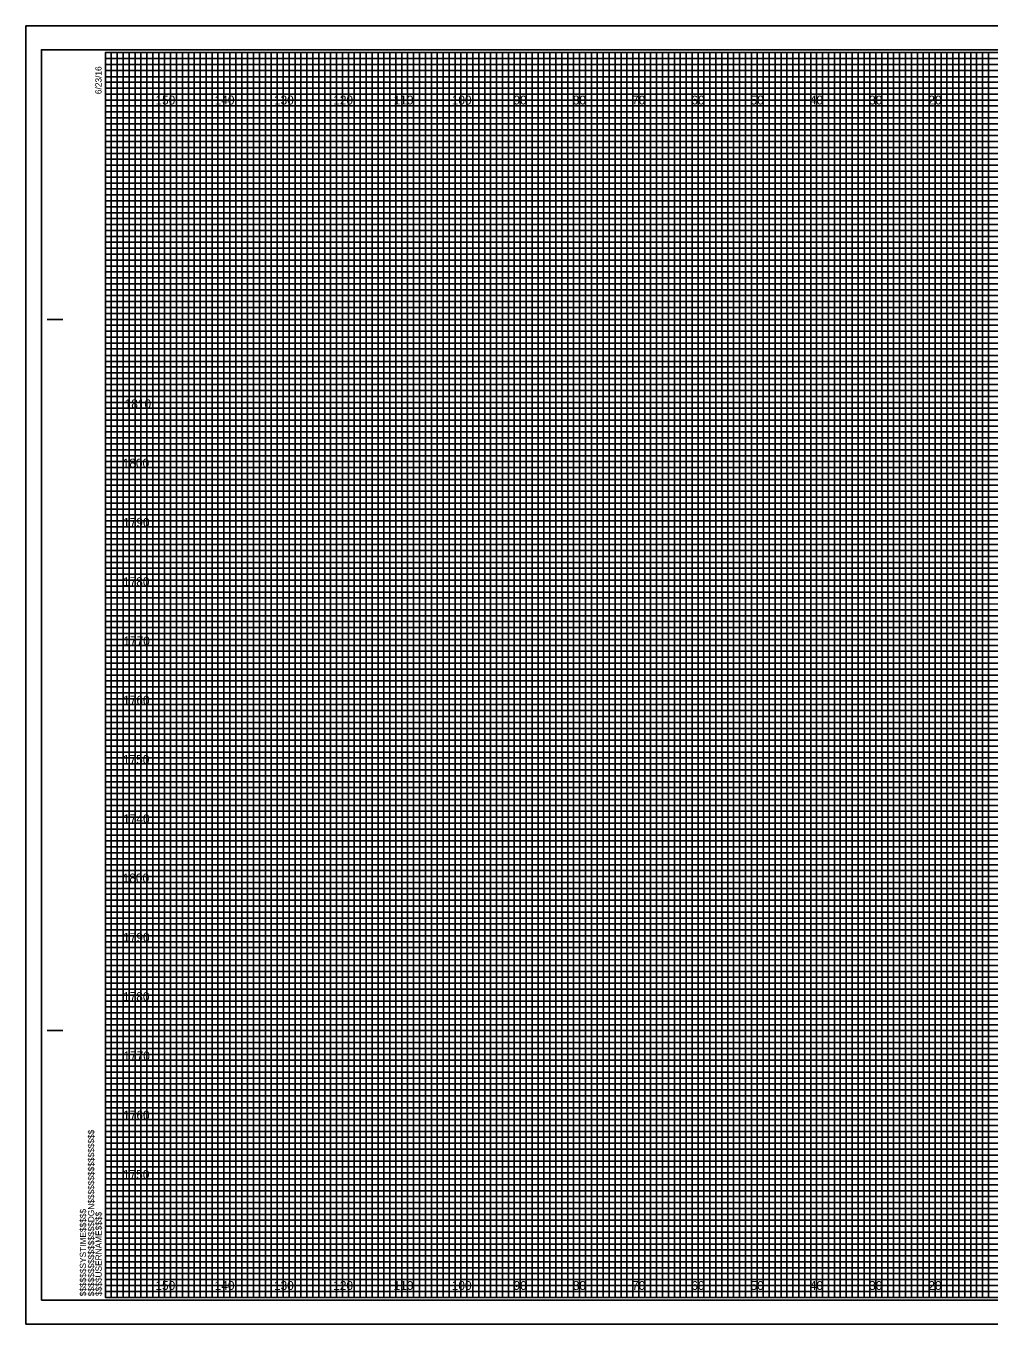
# Model space of a CAD drawing. Extents: x -13 to 323, y -5 to 874.
# Drawn here: x -13.4 to 149.1, y 435.5 to 654.5 of the extents above; entities that cross this region are included whole.
import ezdxf

# ---------------------------------------------------------------- set-up
doc = ezdxf.new("R2010")
doc.units = 0
for name, color, linetype in [('Prop XS DDE', 7, 'Continuous'), ('Prop XS DDE Elevations', 7, 'Continuous'), ('Prop XS DDE Slope Text', 7, 'Continuous'), ('Prop XS Gore Control Minimum', 7, 'Continuous'), ('Prop XS Shoulder Borrow Shape', 7, 'Continuous'), ('Raster_Level_0', 7, 'Continuous'), ('Scratch_Level_3', 7, 'Continuous'), ('Sheet Cutting Line CELL', 7, 'Continuous'), ('Sheet DOT Grid CELL', 7, 'Continuous'), ('Sheet Plot Border Inside CELL', 7, 'Continuous'), ('Sheet Plot Border Outside CELL', 7, 'Continuous')]:
    doc.layers.add(name, color=color, linetype=linetype)

msp = doc.modelspace()

# ---------------------------------------------------------------- linework, layer by layer
at = {"layer": 'Prop XS DDE'}
for p, q in [((0, 649), (260, 649)), ((260, 647.98), (0, 647.98)), ((0, 647.98), (0, 647)), ((0, 647), (260, 647)), ((260, 645.89), (0, 645.89)), ((0, 645.89), (0, 644)), ((0, 644), (320, 644))]:
    msp.add_line(p, q, dxfattribs=at)
for points in [[(0, 643), (270, 643), (320, 643), (320, 642), (0, 642)], [(0, 641), (320, 641), (320, 639), (0, 639)], [(0, 638), (320, 638), (320, 637), (0, 636.98)], [(0, 636), (320, 636), (320, 634), (0, 634)], [(0, 633), (320, 633), (320, 632), (0, 632)], [(0, 631), (320, 631), (320, 629), (0, 629)], [(0, 628), (320, 628), (320, 627), (0, 627)], [(0, 626), (320, 626), (320, 624), (0, 624)], [(0, 623), (320, 623), (320, 622), (0, 622)], [(0, 621), (320, 621), (320, 619), (0, 619)], [(0, 618), (320, 618), (320, 617), (0, 617)], [(0, 616), (320, 616), (320, 613.95), (320, 613), (320, 612), (0, 612)], [(0, 614), (320, 614), (320, 613), (0, 613)], [(0, 611), (320, 611), (320, 609), (0, 609.03)], [(0, 609.03), (320, 609), (320, 608), (0, 608)], [(0, 607), (320, 607), (320, 606), (0, 606)], [(0, 604), (320, 604), (320, 603), (0, 603)], [(0, 602), (320, 602), (320, 601), (0, 601)], [(-0.07, 598.89), (320, 598.89), (320, 597.88), (-0.07, 597.88)], [(0, 597), (320, 597), (320, 596), (0, 596)], [(0, 594), (320, 594), (320, 593), (0, 593)], [(0, 592), (320, 592), (320, 591), (0, 591)], [(0, 589), (320, 589), (320, 588), (0, 588)], [(0, 587), (320, 587), (320, 586), (0, 586)], [(0, 584), (320, 584), (320, 583), (0, 583)], [(0, 582), (320, 582), (320, 581), (0, 581)], [(0, 579), (320, 579), (319.99, 577.98), (0, 578)], [(0, 577), (320, 577), (320, 576), (0, 576)], [(0, 574), (320, 574), (320, 573), (0, 573)], [(0, 572), (320, 572), (320, 571), (0, 571)], [(0, 569), (320, 569), (320, 568), (0, 568)], [(0, 567), (320, 567), (320, 566), (0, 566)], [(0, 564), (320, 564), (320, 563), (0, 563)], [(0, 562), (320, 562), (320, 561), (0, 561)], [(0, 559), (320, 559), (320, 558), (0, 558)], [(0, 556.99), (320.07, 556.91), (320, 556), (0, 556)], [(0, 554), (320, 554), (320, 553), (0, 553)], [(0, 552), (320, 552), (320, 551), (0, 551)], [(0, 549), (320, 549), (320, 548), (0, 548)], [(0, 547), (320, 547), (320, 546), (0, 546)], [(0, 544), (320, 544), (320, 543), (0, 543)], [(0, 542), (320, 542), (320, 541), (0, 541)], [(0, 539), (320, 539), (320, 538), (0, 538)], [(0, 537), (320, 537), (320, 536), (0, 536)], [(0, 534), (320, 534), (320, 533), (0, 533)], [(0, 532), (320, 532), (320, 531), (0, 531)], [(0, 529), (320, 529), (320, 528), (0, 528)], [(0, 527), (320, 527), (320, 526), (0, 526)], [(0, 524), (320, 524), (320, 523), (0, 523)], [(0, 522), (320, 522), (320, 521), (0, 521)], [(0, 519), (320, 519), (319.99, 517.98), (0, 518)], [(0, 517), (320, 517), (320, 516), (0, 516)], [(0, 514), (320, 514), (320, 513), (0, 513)], [(0, 512), (320, 512), (320, 511), (0, 511)], [(0, 509), (320, 509), (320, 508), (0, 508)], [(0, 507), (320, 507), (320, 506), (0, 506)], [(0, 504), (320, 504), (320, 503), (0, 503)], [(0, 502), (320, 502), (320, 501), (0, 501)], [(0, 499), (320, 499), (320, 498), (0, 498)], [(0, 496.99), (320.07, 496.91), (320, 496), (0, 496)], [(0, 494), (320, 494), (320, 493), (0, 493)], [(0, 492), (320, 492), (320, 491), (0, 491)], [(0, 489), (320, 489), (320, 488), (0, 488)], [(0, 487), (320, 487), (320, 486), (0, 486)], [(0, 484), (320, 484), (320, 483), (0, 483)], [(0, 482), (320, 482), (320, 481), (0, 481)], [(0, 479), (320, 479), (320, 478), (0, 478)], [(0, 477), (320, 477), (320, 476), (0, 476)], [(0, 474), (320, 474), (320, 473), (0, 473)], [(0, 472), (320, 472), (320, 471), (0, 471)], [(0, 469), (320, 469), (320, 468), (0, 468)], [(0, 467), (320, 467), (320, 466), (0, 466)], [(0, 464), (320, 464), (320, 463), (0, 463)], [(0, 462), (320, 462), (320, 461), (0, 461)], [(0, 459), (320, 459), (320, 458), (0, 458)], [(0, 457), (320, 457), (320, 456), (0, 456)], [(0, 454), (320, 454), (320, 453), (0, 453)], [(0, 452), (320, 452), (320, 451), (0, 451)], [(0, 449), (320, 449), (320, 448), (0, 448)], [(0, 447), (320, 447), (320, 446), (0, 446)], [(0, 444), (320, 444), (320, 443), (0, 443)], [(0, 442), (320, 442), (320, 441), (0, 441)]]:
    msp.add_lwpolyline(points, dxfattribs=at)
at = {"layer": 'Prop XS DDE Elevations'}
for points in [[(0, 440), (1, 440), (1, 650), (2, 650), (2, 440)], [(2, 440), (3, 440), (3, 650), (4, 650), (4, 440)], [(5, 440), (6, 440), (6, 650), (7, 650), (7, 440)], [(7, 440), (8, 440), (8, 650), (9, 650), (9, 440)], [(10, 440), (11, 440), (11, 650), (12, 650), (12, 440)], [(12, 440), (13, 440), (13, 650), (14, 650), (14, 440)], [(15, 440), (16, 440), (16, 650), (17, 650), (17, 440)], [(17, 440), (18, 440), (18, 650), (19, 650), (19, 440)], [(20, 440), (21, 440), (21, 650), (22, 650), (22, 440)], [(22, 440), (23, 440), (23, 650), (24, 650), (24, 440)], [(25, 440), (26, 440), (26, 650), (27, 650), (27, 440)], [(27, 440), (28, 440), (28, 650), (29, 650), (29, 440)], [(30, 440), (31, 440), (31, 650), (32, 650), (32, 440)], [(32, 440), (33, 440), (33, 650), (34, 650), (34, 440)], [(35, 440), (36, 440), (36, 650), (37, 650), (37, 440)], [(37, 440), (38, 440), (38, 650), (39, 650), (39, 440)], [(40, 440), (41, 440), (41, 650), (42, 650), (42, 440)], [(42, 440), (43, 440), (43, 650), (44, 650), (44, 440)], [(45, 440), (46, 440), (46, 650), (47, 650), (47, 440)], [(47, 440), (48, 440), (48, 650), (49, 650), (49, 440)], [(50, 440), (51, 440), (51, 650), (52, 650), (52, 440)], [(52, 440), (53, 440), (53, 650), (54, 650), (54, 440)], [(55, 440), (56, 440), (56, 650), (57, 650), (57, 440)], [(57, 440), (58, 440), (58, 650), (59, 650), (59, 440)], [(60, 440), (61, 440), (61, 650), (62, 650), (62, 440)], [(62, 440), (63, 440), (63, 650), (64, 650), (64, 440)], [(65, 440), (66, 440), (66, 650), (67, 650), (67, 440)], [(67, 440), (68, 440), (68, 650), (69, 650), (69, 440)], [(70, 440), (71, 440), (71, 650), (72, 650), (72, 440)], [(72, 440), (73, 440), (73, 650), (74, 650), (74, 440)], [(75, 440), (76, 440), (76, 650), (77, 650), (77, 440)], [(77, 440), (78, 440), (78, 650), (79, 650), (79, 440)], [(80, 440), (81, 440), (81, 650), (82, 650), (82, 440)], [(82, 440), (83, 440), (83, 650), (84, 650), (84, 440)], [(85, 440), (86, 440), (86, 650), (87, 650), (87, 440)], [(87, 440), (88, 440), (88, 650), (89, 650), (89, 440)], [(90, 440), (91, 440), (91, 650), (92, 650), (92, 440)], [(92, 440), (93, 440), (93, 650), (94, 650), (94, 440)], [(95, 440), (96, 440), (96, 650), (97, 650), (97, 440)], [(97, 440), (98, 440), (98, 650), (99, 650), (99, 440)], [(100, 440), (101, 440), (101, 650), (102, 650), (102, 440)], [(102, 440), (103, 440), (103, 650), (104, 650), (104, 440)], [(105, 440), (106, 440), (106, 650), (107, 650), (107, 440)], [(107, 440), (108, 440), (108, 650), (109, 650), (109, 440)], [(110, 440), (111, 440), (111, 650), (112, 650), (112, 440)], [(112, 440), (113, 440), (113, 650), (114, 650), (114, 440)], [(115, 440), (116, 440), (116, 650), (117, 650), (117, 440)], [(117, 440), (118, 440), (118, 650), (119, 650), (119, 440)], [(120, 440), (121, 440), (121, 650), (122, 650), (122, 440)], [(122, 440), (123, 440), (123, 650), (124, 650), (124, 440)], [(125, 440), (126, 440), (126, 650), (127, 650), (127, 440)], [(127, 440), (128, 440), (128, 650), (129, 650), (129, 440)], [(130, 440), (131, 440), (131, 650), (132, 650), (132, 440)], [(132, 440), (133, 440), (133, 650), (134, 650), (134, 440)], [(135, 440), (136, 440), (136, 650), (137, 650), (137, 440)], [(137, 440), (138, 440), (138, 650), (139, 650), (139, 440)], [(140, 440), (141, 440), (141, 650), (142, 650), (142, 440)], [(142, 440), (143, 440), (143, 650), (144, 650), (144, 440)], [(145, 440), (146, 440), (146, 650), (147, 650), (147, 440)], [(147, 440), (148, 440), (148, 650), (149, 650), (149, 440)]]:
    msp.add_lwpolyline(points, dxfattribs=at)
at = {"layer": 'Prop XS DDE Slope Text'}
for p, q in [((-9.8, 605), (-7.3, 605)), ((-9.7, 605), (-7.2, 605)), ((-9.8, 485), (-7.3, 485)), ((-9.7, 485), (-7.2, 485)), ((0, 440), (0, 440)), ((0, 440), (0, 440)), ((0, 440), (0, 440)), ((0, 440), (0, 440)), ((0, 440), (0, 440)), ((0, 440), (0, 440)), ((0, 440), (0, 440))]:
    msp.add_line(p, q, dxfattribs=at)
msp.add_lwpolyline([(320, 650), (0, 650), (0, 440), (320, 440)], close=True, dxfattribs=at)
at = {"layer": 'Prop XS Gore Control Minimum'}
for p, q in [((10, 650), (0, 650)), ((10, 440), (10, 650)), ((30, 650), (20, 650)), ((20, 650), (20, 440)), ((30, 440), (30, 650)), ((50, 650), (40, 650)), ((40, 650), (40, 440)), ((50, 440), (50, 650)), ((70, 650), (60, 650)), ((60, 650), (60, 440)), ((70, 440), (70, 650)), ((90, 650), (80, 650)), ((80, 650), (80, 440)), ((90, 440), (90, 650)), ((110, 650), (100, 650)), ((100, 650), (100, 440)), ((110, 440), (110, 650)), ((130, 650), (120, 650)), ((120, 650), (120, 440)), ((130, 440), (130, 650)), ((150, 650), (140, 650)), ((140, 650), (140, 440)), ((20, 440), (10, 440)), ((40, 440), (30, 440)), ((60, 440), (50, 440)), ((80, 440), (70, 440)), ((100, 440), (90, 440)), ((120, 440), (110, 440)), ((140, 440), (130, 440))]:
    msp.add_line(p, q, dxfattribs=at)
for points in [[(0, 640), (320, 640), (320, 630), (0, 630)], [(0, 620), (320, 620), (320, 610), (0, 610)], [(0, 600), (320, 600), (320, 590), (0, 590)], [(0, 580), (320, 580), (320, 570), (0, 570)], [(0, 560), (320, 560), (320, 550), (0, 550)], [(0, 540), (320, 540), (320, 530), (0, 530)], [(0, 520), (320, 520), (320, 510), (0, 510)], [(0, 500), (320, 500), (320, 490), (0, 490)], [(0, 480), (320, 480), (320, 470), (0, 470)], [(0, 460), (320, 460), (320, 450), (0, 450)]]:
    msp.add_lwpolyline(points, dxfattribs=at)
at = {"layer": 'Prop XS Shoulder Borrow Shape'}
for points in [[(0, 650), (5, 650), (5, 440), (15, 440), (15, 650), (25, 650), (25, 440), (35, 440), (35, 650), (45, 650), (45, 440), (55, 440), (55, 650), (65, 650), (65, 440), (75, 440), (75, 650), (85, 650), (85, 440), (95, 440), (95, 650), (105, 650), (105, 440), (115, 440), (115, 650), (125, 650), (125, 440), (135, 440), (135, 650), (145, 650), (145, 440), (155, 440)], [(0, 645), (275, 645)], [(0, 625), (320, 625), (320, 635), (0, 635)], [(0, 605), (320, 605), (320, 615), (0, 615)], [(0, 585), (320, 585), (320, 595), (0, 595)], [(0, 565), (320, 565), (320, 575), (0, 575)], [(0, 545), (320, 545), (320, 555), (0, 555)], [(0, 525), (320, 525), (320, 535), (0, 535)], [(0, 505), (320, 505), (320, 515), (0, 515)], [(0, 485), (320, 485), (320, 495), (0, 495)], [(0, 465), (320, 465), (320, 475), (0, 475)], [(0, 445), (320, 445), (320, 455), (0, 455)]]:
    msp.add_lwpolyline(points, dxfattribs=at)
at = {"layer": 'Sheet Cutting Line CELL'}
for p, q in [((323.3, 654.5), (-13.4, 654.5)), ((-13.4, 654.5), (-13.4, 435.5)), ((-13.4, 435.5), (323.3, 435.5))]:
    msp.add_line(p, q, dxfattribs=at)
at = {"layer": 'Sheet DOT Grid CELL'}
for p, q in [((10, 440), (10, 650)), ((20, 440), (20, 650)), ((30, 440), (30, 650)), ((40, 440), (40, 650)), ((50, 440), (50, 650)), ((60, 440), (60, 650)), ((70, 440), (70, 650)), ((80, 440), (80, 650)), ((90, 440), (90, 650)), ((100, 440), (100, 650)), ((110, 440), (110, 650)), ((120, 440), (120, 650)), ((130, 440), (130, 650)), ((140, 440), (140, 650)), ((0, 640), (320, 640)), ((0, 630), (320, 630)), ((0, 620), (320, 620)), ((0, 610), (320, 610)), ((0, 600), (320, 600)), ((0, 590), (320, 590)), ((0, 580), (320, 580)), ((0, 570), (320, 570)), ((0, 560), (320, 560)), ((0, 550), (320, 550)), ((0, 540), (320, 540)), ((0, 530), (320, 530)), ((0, 520), (320, 520)), ((0, 510), (320, 510)), ((0, 500), (320, 500)), ((0, 490), (320, 490)), ((0, 480), (320, 480)), ((0, 470), (320, 470)), ((0, 460), (320, 460)), ((0, 450), (320, 450))]:
    msp.add_line(p, q, dxfattribs=at)
at = {"layer": 'Sheet Plot Border Inside CELL'}
msp.add_lwpolyline([(-10.8, 439.5), (322.4, 439.5), (322.4, 650.5), (-10.8, 650.5)], close=True, dxfattribs=at)
at = {"layer": 'Sheet Plot Border Outside CELL'}
msp.add_lwpolyline([(-13.4, 435.5), (323.3, 435.5), (323.3, 654.5), (-13.4, 654.5)], close=True, dxfattribs=at)

# ---------------------------------------------------------------- texts
at = {"layer": 'Prop XS DDE Slope Text'}
for s, p in [('6/23/16', (-0.65, 643)), ('$$$$$$$$$$$$$$$$DGN$$$$$$$$$$$$$$$$', (-1.88, 440.18)), ('$$$$$$SYSTIME$$$$$', (-3.26, 440.18)), ('$$$$USERNAME$$$$', (-0.62, 440.23))]:
    msp.add_text(s, height=1.05, rotation=90, dxfattribs=at).set_placement(p)
at = {"layer": 'Raster_Level_0'}
for s, p in [('150', (8.44, 641.25)), ('140', (18.44, 641.25)), ('130', (28.44, 641.25)), ('120', (38.44, 641.25)), ('110', (48.62, 641.25)), ('100', (58.44, 641.25)), ('90', (68.86, 641.25)), ('80', (78.86, 641.25)), ('70', (88.86, 641.25)), ('60', (98.86, 641.25)), ('50', (108.86, 641.25)), ('40', (118.86, 641.25)), ('30', (128.86, 641.25)), ('20', (138.86, 641.25)), ('150', (8.44, 441.25)), ('140', (18.44, 441.25)), ('130', (28.44, 441.25)), ('120', (38.44, 441.25)), ('110', (48.62, 441.25)), ('100', (58.44, 441.25)), ('90', (68.86, 441.25)), ('80', (78.86, 441.25)), ('70', (88.86, 441.25)), ('60', (98.86, 441.25)), ('50', (108.86, 441.25)), ('40', (118.86, 441.25)), ('30', (128.86, 441.25)), ('20', (138.86, 441.25))]:
    msp.add_text(s, height=1.5, dxfattribs=at).set_placement(p)
at = {"layer": 'Scratch_Level_3'}
for s, p in [('1810', (3.25, 590)), ('1800', (2.92, 580)), ('1790', (3, 570)), ('1780', (2.98, 560)), ('1770', (3.04, 550)), ('1760', (3, 540)), ('1750', (2.96, 530)), ('1740', (3, 520)), ('1800', (2.92, 510)), ('1790', (3, 500)), ('1780', (2.98, 490)), ('1770', (3.04, 480)), ('1760', (3, 470)), ('1750', (2.96, 460))]:
    msp.add_text(s, height=1.5, dxfattribs=at).set_placement(p)

doc.saveas('drawing.dxf')
